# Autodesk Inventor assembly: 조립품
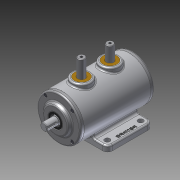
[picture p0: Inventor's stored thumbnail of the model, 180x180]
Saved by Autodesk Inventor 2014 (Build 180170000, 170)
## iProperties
Created: 2014-12
Part Number: 조립품
Document SubType Name: Assembly
Designer: Owner
Author: Owner
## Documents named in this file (10)
- C:\Users\Owner\Desktop\441223V1019\조립품.iam
- C:\Users\Owner\Desktop\441223V1019\본체.ipt
- C:\Users\Owner\Desktop\441223V1019\M4-소켓머리.ipt
- C:\Users\Owner\Desktop\441223V1019\뒷커버.ipt
- C:\Users\Owner\Desktop\441223V1019\베어링 6203.ipt
- C:\Users\Owner\Desktop\441223V1019\부시.ipt
- C:\Users\Owner\Desktop\441223V1019\슬라이더.ipt
- C:\Users\Owner\Desktop\441223V1019\앞커버.ipt
- C:\Users\Owner\Desktop\441223V1019\오일실.ipt
- C:\Users\Owner\Desktop\441223V1019\축.ipt
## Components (11 placed, 3 different names)
1. 8-오일실:1
2. 7-베어링 6203:2
3. 7-베어링 6203:3
4. 9-M4-소켓머리:1
5. 9-M4-소켓머리:3
6. 9-M4-소켓머리:4
7. 9-M4-소켓머리:5
8. 9-M4-소켓머리:2
9. 9-M4-소켓머리:6
10. 9-M4-소켓머리:7
11. 9-M4-소켓머리:8
